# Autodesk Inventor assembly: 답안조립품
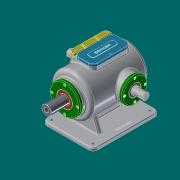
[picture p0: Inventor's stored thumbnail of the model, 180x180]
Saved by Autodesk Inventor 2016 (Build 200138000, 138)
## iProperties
Created: 2018-08
Part Number: 답안조립품
Material: 일반
Document SubType Name: Assembly
Designer: 605-04
Mass: 7432.52 g
Surface Area: 4486.62 cm^2
Volume: 2026.91 cm^3
Density: 3.66692 g/cm^3
Author: 605-04
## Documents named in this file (15)
- C:\Users\605-04\Desktop\380808V1004\공용부품_20180825_1\답안조립품.iam
- C:\Users\605-04\Desktop\380808V1004\공용부품_20180825_1\가변스프링.ipt
- C:\Users\605-04\Desktop\380808V1004\공용부품_20180825_1\고정플레이트.ipt
- C:\Users\605-04\Desktop\380808V1004\공용부품_20180825_1\베어링 6205.ipt
- 베어링 6205.ipt
- C:\Users\605-04\Desktop\380808V1004\공용부품_20180825_1\본체.ipt
- C:\Users\605-04\Desktop\380808V1004\공용부품_20180825_1\볼트 M4x0.7.ipt
- C:\Users\605-04\Desktop\380808V1004\공용부품_20180825_1\부시.ipt
- C:\Users\605-04\Desktop\380808V1004\공용부품_20180825_1\상부커버.ipt
- C:\Users\605-04\Desktop\380808V1004\공용부품_20180825_1\슬라이드 커버.ipt
- C:\Users\605-04\Desktop\380808V1004\공용부품_20180825_1\슬라이드.ipt
- C:\Users\605-04\Desktop\380808V1004\공용부품_20180825_1\오일 실 25 38 8.ipt
- C:\Users\605-04\Desktop\380808V1004\공용부품_20180825_1\육각머리볼트 M4.ipt
- C:\Users\605-04\Desktop\380808V1004\공용부품_20180825_1\축 커버.ipt
- C:\Users\605-04\Desktop\380808V1004\공용부품_20180825_1\편심축.ipt
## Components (14 placed, 3 different names)
1. 가변스프링:1
2. 고정플레이트:1 — 플러쉬:1
3. M4x0.7:1
4. M4x0.7:4
5. M4x0.7:5
6. M4x0.7:6
7. M4x0.7:3
8. M4x0.7:7
9. M4x0.7:8
10. M4x0.7:9
11. M4x0.7:2
12. M4x0.7:10
13. M4x0.7:11
14. M4x0.7:12
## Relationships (1: Flush 1)
- 플러쉬:1 [Flush]: 고정플레이트:1
